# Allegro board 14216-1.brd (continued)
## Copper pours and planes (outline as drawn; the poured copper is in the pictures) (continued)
PWR_5V_LL1 on TOP: 41.57,40.15 41.46,40.26 41.46,41.17 41.68,41.38 43.13,41.38 43.44,41.69 43.44,44.73 43.57,44.85 47.63,44.85 47.76,44.73 47.76,43.46 48.01,43.2 50.3,43.2 50.43,43.08 50.43,40.28 50.3,40.15
PWR_5V_LL1 on BOTTOM: 44.3,40.13 43.7,40.74 43.7,44.35 44.08,44.73 49.79,44.73 50.3,44.22 50.3,40.41 50.02,40.13
PWR_CHG_HIDRV on BOTTOM: 124.49,156.8 126.5,156.8 126.58,156.72 126.58,156.04 126.5,155.96 124.59,155.96 124.44,156.11 124.44,156.75
PWR_CHG_LODRV on BOTTOM: 120.63,162.89 120.53,163 120.53,163.45 120.61,163.53 122.36,163.53 122.46,163.43 122.46,162.92 122.44,162.89
PWR_CHG_PHASE on BOTTOM: 124.54,156.98 124.44,157.08 124.44,159.77 124.14,160.08 123.17,160.08 122.79,160.46 122.79,163.7 123.02,163.93 126.6,163.93 129.04,161.49 129.04,157.59 128,156.54 127.24,156.54 126.8,156.98
PWR_DCBATOUT_1D05V on TOP: 131.99,132.87 131.74,133.12 131.74,138.96 132.12,139.35 135.42,139.35 135.55,139.22 135.55,133 135.42,132.87 ; 2 cut-outs
PWR_DCBATOUT_1D05V on BOTTOM: 132.34,137.26 132.07,137.54 132.07,139.32 132.09,139.35 134.22,139.35 134.58,138.99 134.58,137.49 134.35,137.26
PWR_DCBATOUT_3D3V on TOP: 30.87,43.46 30.21,44.12 30.21,50.4 30.25,50.44 34.42,50.44 34.55,50.31 34.55,43.71 34.3,43.46 ; 2 cut-outs
PWR_DCBATOUT_3D3V on BOTTOM: 34.55,50.44 34.68,50.31 34.68,47.39 34.42,47.14 31.26,47.14 31.04,47.35 31.04,50.07 31.42,50.44
PWR_DCBATOUT_5V on TOP: 48.27,43.46 48.01,43.71 48.01,46.89 47.76,47.14 47.76,51.2 48.14,51.58 51.82,51.58 51.82,43.58 51.7,43.46 ; 2 cut-outs
PWR_DCBATOUT_5V on BOTTOM: 48.27,46.5 48.01,46.76 48.01,47.9 47.76,48.16 47.76,50.06 47.89,50.19 49.92,50.19 50.55,49.55 50.55,46.76 50.3,46.5
PWR_DCBATOUT_VCCCORE on TOP: 115.5,129.44 115.17,129.77 115.17,134.14 115.3,134.27 115.81,134.27 115.82,134.26 117.58,134.26 117.84,134 117.84,129.69 117.58,129.44
PWR_DCBATOUT_VCCCORE on BOTTOM: 115.81,126.01 115.68,126.14 115.68,127.54 115.55,127.66 112.88,127.66 112.63,127.92 112.63,134.78 112.76,134.9 116.47,134.9 116.64,135.07 117.83,135.07 117.96,134.94 117.96,131.98 117.84,131.86 116.82,131.86 116.57,131.6 116.57,126.14 116.44,126.01 ; 2 cut-outs
PWR_DCBATOUT_VGA_CORE1 on TOP: 163.28,92.17 163.02,92.43 163.02,98.14 166.83,98.14 167.22,97.76 173.18,97.76 173.31,97.64 173.31,92.43 173.06,92.17
PWR_DCBATOUT_VGA_CORE1 on BOTTOM: 163.41,92.17 162.9,92.68 162.9,98.02 163.02,98.14 167.72,98.14 168.1,97.76 173.18,97.76 173.31,97.64 173.31,92.3 173.18,92.17 ; 2 cut-outs
PWR_DCBATOUT_VGA_CORE2 on TOP: 167.98,115.29 167.6,115.67 162.52,115.67 162.29,115.9 162.29,120.44 162.36,120.51 164.33,120.51 164.67,120.86 173.24,120.86 173.31,120.79 173.31,115.42 173.18,115.29
PWR_DCBATOUT_VGA_CORE2 on BOTTOM: 167.98,115.29 167.6,115.67 163.02,115.67 162.9,115.8 162.9,120.05 163.1,120.25 166.08,120.25 166.64,120.81 173.25,120.81 173.31,120.74 173.31,115.42 173.18,115.29 ; 2 cut-outs
PWR_VCC_LG on BOTTOM: 120.5,125.38 120.25,125.63 120.25,127.21 120.3,127.26 121.32,127.26 121.39,127.18 121.39,125.51 121.27,125.38
PWR_VCC_PHASE on BOTTOM: 114.26,121.34 114.15,121.44 114.15,124.62 114.41,124.87 115.93,124.87 116.95,125.89 116.95,131.35 117.08,131.47 119.87,131.47 120,131.35 120,125.38 120.89,124.49 120.89,121.44 120.78,121.34
PWR_VCC_UG on BOTTOM: 114.41,125.38 114.26,125.53 114.26,127.21 114.31,127.26 115.27,127.26 115.3,127.23 115.3,125.51 115.17,125.38
PWR_VGA_CORE_LGATE1 on TOP: 168.23,98.27 168.1,98.4 168.1,99.92 169.63,99.92 169.63,98.4 169.5,98.27
PWR_VGA_CORE_LGATE1 on BOTTOM: 168.1,102.97 168.1,104.49 168.23,104.62 169.5,104.62 169.63,104.49 169.63,102.97
PWR_VGA_CORE_LGATE2 on TOP: 168.23,108.56 168.1,108.68 168.1,110.21 169.63,110.21 169.63,108.68 169.5,108.56
PWR_VGA_CORE_LGATE2 on BOTTOM: 168.1,113.26 168.1,114.78 168.23,114.91 169.5,114.91 169.63,114.78 169.63,113.26
PWR_VGA_CORE_PHASE1 on TOP: 173.82,92.43 173.69,92.56 173.69,95.86 173.82,95.98 176.23,95.98 176.49,96.24 176.49,97.13 175.85,97.76 173.82,97.76 173.44,98.14 170.26,98.14 170.01,98.4 170.01,105.13 170.9,106.02 178.9,106.02 179.03,106.02 179.17,105.88 179.17,94.47 177.12,92.43
PWR_VGA_CORE_PHASE1 on BOTTOM: 173.82,93.95 173.69,94.08 173.69,97.89 173.44,98.14 170.26,98.14 170.01,98.4 170.01,103.99 170.14,104.11 173.82,104.11 174.2,104.49 174.2,106.3 174.31,106.42 175.25,106.42 175.27,106.4 175.27,106.13 175.37,106.02 178.98,106.02 179.17,105.83 179.17,94.47 178.65,93.95
PWR_VGA_CORE_PHASE1 on L3: 173.82,93.95 173.69,94.08 173.69,97.89 173.44,98.14 170.26,98.14 170.01,98.4 170.01,103.99 170.14,104.11 178.91,104.11 179.17,103.86 179.17,94.47 178.65,93.95
PWR_VGA_CORE_PHASE2 on TOP: 170.64,106.78 170.14,107.29 170.14,114.4 170.26,114.53 173.44,114.53 173.69,114.78 173.69,119.04 173.69,119.04 173.69,119.21 173.72,119.24 177.35,119.24 179.04,117.54 179.04,117.32 179.05,117.31 179.05,107.13 178.7,106.78
PWR_VGA_CORE_PHASE2 on BOTTOM: 174.31,106.76 174.2,106.88 174.2,108.94 174.07,109.07 170.26,109.07 170.14,109.19 170.14,114.4 170.26,114.53 174.71,114.53 175.6,115.42 176.11,115.42 176.36,115.67 176.36,116.81 176.11,117.07 173.82,117.07 173.69,117.19 173.69,120.39 173.9,120.6 176,120.6 179.05,117.56 179.05,109.88 179.04,109.87 179.04,107.13 178.68,106.77 175.26,106.77 175.25,106.76
PWR_VGA_CORE_PHASE2 on L3: 170.26,109.07 170.14,109.19 170.14,114.4 170.26,114.53 173.57,114.53 173.69,114.65 173.69,120.39 173.9,120.6 176,120.6 179.05,117.56 179.05,109.88 179.05,109.88 179.05,109.38 178.73,109.07
PWR_VGA_CORE_UGATE1 on TOP: 173.69,96.49 173.69,97.25 175.98,97.25 176.11,97.13 176.11,96.62 175.98,96.49
PWR_VGA_CORE_UGATE1 on BOTTOM: 173.69,92.68 173.69,93.44 175.98,93.44 176.11,93.32 176.11,92.81 175.98,92.68
PWR_VGA_CORE_UGATE2 on TOP: 173.79,119.61 173.69,119.71 173.69,120.47 173.73,120.51 175.89,120.51 176.11,120.3 176.11,119.73 175.98,119.61
PWR_VGA_CORE_UGATE2 on BOTTOM: 173.69,115.8 173.69,116.56 175.98,116.56 176.11,116.43 176.11,115.92 175.98,115.8
PWR_VGA_SNUB1 on BOTTOM: 170.66,104.86 170.52,105 170.52,106.4 170.64,106.53 173.48,106.53 173.58,106.42 173.58,104.87 173.57,104.86 ; 2 cut-outs
PWR_VGA_SNUB2 on BOTTOM: 170.79,106.77 170.52,107.03 170.52,108.18 170.77,108.43 173.44,108.43 173.47,108.43 173.58,108.32 173.58,106.77 173.58,106.77 ; 2 cut-outs
REGOUT on TOP: 50.61,170.23 50.57,170.27 50.57,171.42 50.84,171.69 50.84,174.42 51.09,174.67 55.71,174.67 56.04,174.34 56.04,173.04 55.83,172.84 53.68,172.84 53.67,172.84 52.9,172.84 52.75,172.69 52.75,171.39 51.6,170.23 ; 4 cut-outs
RING2 on BOTTOM: 182.52,18.83 182.51,18.83 182.51,19.96 182.08,20.4 182.08,23.6 182.21,23.73 182.76,23.73 182.89,23.6 182.89,21.65 182.73,21.48 182.73,18.85 182.72,18.83 ; 1 cut-out
RING2_R on TOP: 184.61,21.62 184.51,21.72 184.51,22.53 184.61,22.64 187.26,22.64 188.96,24.34 189.67,24.34 190.35,25.02 192.08,25.02 192.13,24.97 192.13,24.59 192.08,24.54 190.69,24.54 190.66,24.52 190.66,24.03 190.71,23.98 192.11,23.98 192.13,23.96 192.13,23.55 192.11,23.52 190.3,23.52 188.39,21.62
RTC_AUX_S5 on TOP: 136.74,58.37 136,59.11 136,66.68 130.75,71.93 130.75,73.66 130.79,73.71 131.45,73.71 131.52,73.64 131.52,72.35 136.63,67.24 136.63,62.72 137.24,62.11 137.24,59.59 137.93,58.91 139.12,58.91 139.41,59.19 139.41,64 139.66,64.24 140.75,64.24 141.56,63.43 141.56,62.45 141.81,62.2 142.79,62.2 142.88,62.11 142.88,59.9 142.87,59.89 142.87,59.35 141.88,58.37 ; 4 cut-outs
RTC_AUX_S5 on BOTTOM: 140.27,59.31 140.16,59.42 140.16,62.44 140.11,62.49 140.11,62.89 140.16,62.95 140.52,62.95 140.75,62.72 140.75,59.42 140.65,59.31
SLEEVE on BOTTOM: 182.92,18.83 182.89,18.85 182.89,21.47 183.05,21.62 183.05,23.86 182.62,24.29 182.62,24.51 182.77,24.66 183.09,24.66 183.86,23.89 183.86,23.6 183.86,23.6 183.86,21.43 183.15,20.72 183.15,18.85 183.12,18.83
SLEEVE_R on TOP: 184.64,23.02 184.54,23.12 184.54,23.98 184.59,24.03 185.55,24.03 187.32,25.81 189.49,25.81 190.71,27.03 192.08,27.03 192.13,26.98 192.13,26.57 192.11,26.55 190.76,26.55 190.71,26.5 190.71,26.06 190.79,25.99 192.11,25.99 192.16,25.94 192.16,25.56 192.13,25.53 190.51,25.53 189.6,24.62 188.73,24.62 187.13,23.02
SP_PLLVDD on TOP: 167,129.24 166.92,129.32 166.92,133.22 165.86,134.27 165.73,134.27 165.59,134.41 165.59,135.28 165.72,135.41 166.17,135.41 166.17,135.41 167.61,135.41 167.88,135.14 167.88,135.14 167.95,135.06 167.95,134.19 168.13,134.01 168.13,133.38 168.3,133.21 168.3,129.53 168,129.24 ; 7 cut-outs
SYS_PRES1# on TOP: 155.74,176.39 155.44,176.68 155.44,180.13 155.53,180.22 156.58,180.22 156.58,180.22 156.66,180.14 156.66,176.49 156.56,176.39
TP_VDD on TOP: 48.58,69.42 48.45,69.54 48.45,70.26 48.57,70.38 55.54,70.38 58.14,72.98 60.04,72.98 61.12,74.06 62.2,74.06 62.29,73.98 63.6,73.98 63.6,73.96 63.69,73.87 63.69,73.64 63.56,73.51 61.77,73.51 60.23,71.97 58.2,71.97 55.65,69.42
TP_VDD on TOP: 48.32,75.41 48.07,75.66 48.07,78.86 48.31,79.1 52.12,79.1 52.38,78.84 52.38,77.23 52.27,77.13 50.89,77.13 49.18,75.41 ; 6 cut-outs
TP_VDD on TOP: 56.13,74.38 56.09,74.42 56.09,76.18 56.17,76.26 57.19,76.26 57.24,76.21 57.24,74.46 57.15,74.38
TP_VDD on L3: 51.25,79.14 52.6,79.14 55.47,76.27 57.38,76.27 57.79,75.86 59.29,75.86 59.87,75.29 59.87,72.3 59.62,72.05 59.26,72.05 58.92,72.39 58.92,74.62 58.31,75.23 55.42,75.23 52.3,78.35 51.25,78.35 51.08,78.53 51.08,78.97
TPAN_VDD on TOP: 77.8,156.74 76.6,157.94 76.6,162.05 76.69,162.14 77.66,162.14 77.81,161.99 77.81,157.62 77.96,157.47 78.84,157.47 78.89,157.42 78.89,156.77 78.86,156.74
TPAN_VDD on BOTTOM: 77.45,160.56 76.82,161.19 71.86,161.19 71.61,161.45 71.61,163.86 71.74,163.99 76.31,163.99 78.09,162.21 78.09,160.81 77.83,160.56 ; 2 cut-outs
TPAN_VDD_F on BOTTOM: 75.67,157.26 74.68,158.25 71.76,158.25 71.48,158.53 71.48,160.05 72.24,160.81 76.82,160.81 78.34,159.29 78.34,157.38 78.21,157.26 ; 5 cut-outs
TPS51216_PHS_SET on TOP: 70.47,14.63 70.09,15.02 69.04,15.02 68.92,15.14 68.92,15.68 69.02,15.78 70.09,15.78 70.47,16.16 71.61,16.16 71.69,16.08 71.69,14.71 71.61,14.63
USB20_VCCA on TOP: 188.46,31.54 187.93,32.08 187.93,34.53 188.07,34.68 189.42,34.68 190.76,36.02 194.65,36.02 194.85,35.82 194.85,32.82 193.57,31.54 ; 4 cut-outs
USB20_VCCA on BOTTOM: 195.54,19.44 195.43,19.54 195.43,29.91 192.94,32.41 192.94,34.35 193.19,34.6 196.27,34.6 198.99,31.89 198.99,24.45 198.08,23.54 198.06,23.54 198,23.47 198,19.54 197.9,19.44
USB30_VCCC on TOP: 18.48,42.04 18.08,42.44 14.58,42.44 13.94,43.08 13.94,45.06 14.35,45.46 23.87,45.46 24.18,45.15 24.18,42.92 23.31,42.05 22.97,42.05 22.97,42.04
USB30_VCCC on BOTTOM: 23.33,42.5 22.88,42.96 15.41,42.96 15.29,43.07 14.38,43.07 13.95,43.5 13.95,44.86 14.54,45.45 22.5,45.45 22.8,45.15 23.57,45.15 23.92,44.8 25.85,44.8 25.99,44.66 25.99,43.44 25.98,43.43 25.98,43.1 25.39,42.5 ; 6 cut-outs
VGA_CORE on TOP: 167.01,139.94 166.85,140.1 166.43,140.1 166.32,139.99 162.66,139.99 162.42,140.23 162.42,140.95 162.48,141.01 169.42,141.01 169.63,140.8 169.63,140.21 169.53,140.12 168.39,140.12 168.22,139.94 ; 1 cut-out
VGA_CORE on TOP: 162.54,125.51 162.41,125.63 162.41,129.32 162.54,129.44 166.61,129.44 166.99,129.06 169.15,129.06 169.4,128.81 169.4,128.55 169.39,128.54 169.39,127.61 168.8,127.02 168.8,126.2 168.59,125.99 164.23,125.99 163.75,125.51 ; 4 cut-outs
VGA_CORE on TOP: 180.2,120.18 180.2,120.19 180.2,120.51 180.55,120.86 185.15,120.86 185.44,120.57 185.44,117.62 185.65,117.41 187.17,117.41 187.59,116.99 187.59,96.35 187.6,96.34 186.13,94.86 184.93,94.86 184.92,94.85 184.49,94.85 182.94,93.3 182.94,92.26 182.66,91.98 180.5,91.98 180.2,92.28
VGA_CORE on TOP: 160.47,142.3 160.39,142.38 160.39,143.35 160.52,143.48 161.28,143.48 161.79,142.97 162.8,142.97 163.2,143.38 164.28,143.38 164.4,143.26 164.91,143.26 165.03,143.38 166.23,143.38 166.4,143.21 166.78,143.21 167.49,143.93 167.89,143.93 168.65,143.16 169.45,143.16 169.59,143.03 169.59,142.44 169.45,142.3 169.45,142.3 161.89,142.3 161.89,142.3 ; 5 cut-outs
VGA_CORE on TOP: 167.22,137.65 166.78,138.09 166.47,138.09 166.04,137.66 165.2,137.66 164.8,138.06 164.44,138.06 164.17,137.78 163.09,137.78 163.09,137.78 163.09,138.08 162.89,138.28 161.37,138.28 161.3,138.35 161.3,138.95 161.44,139.09 162.82,139.09 163.17,138.74 164.19,138.74 164.41,138.95 164.89,138.95 165.08,138.76 166.12,138.76 166.31,138.95 166.79,138.95 167.12,138.61 168.22,138.61 168.56,138.95 168.84,138.95 168.98,138.81 168.98,138.35 168.72,138.09 168.5,138.09 168.06,137.65 ; 2 cut-outs
VGA_CORE on BOTTOM: 180.2,120 181.04,120.84 181.04,121.26 188.98,121.26 189.21,121.03 189.21,119.48 188.22,118.49 188.22,113.34 188.22,113.34 188.22,112.56 188.66,112.12 189.31,112.12 189.5,111.93 189.5,110.66 189.46,110.62 188.47,110.62 187.9,110.05 187.9,105.68 189.34,104.23 189.46,104.23 189.54,104.15 189.54,95.03 189.38,94.87 187.68,94.87 186.54,93.73 184.06,93.73 182.33,92 180.47,92 180.2,92.28 ; 2 cut-outs
VGA_CORE on BOTTOM: 159.44,112.96 159.38,113.02 159.38,120.93 163.33,124.88 168.25,124.88 168.38,124.75 168.38,124.02 168.24,123.88 168.2,123.88 167.04,122.72 164.41,122.72 163.49,121.8 163.08,121.8 162.95,121.94 162.95,122.37 163.91,123.33 163.91,123.79 163.82,123.88 163.34,123.88 159.94,120.48 159.94,113.03 159.87,112.96 ; 1 cut-out
VGA_CORE on BOTTOM: 161.95,134.88 161.31,135.52 161.31,143.9 162.46,145.04 162.84,145.04 163.09,144.79 163.09,144.66 161.7,143.26 161.7,143.14 162.08,142.76 162.33,142.76 164.24,144.66 164.62,144.66 164.74,144.53 164.74,144.28 161.7,141.23 161.7,140.98 161.95,140.72 162.33,140.72 166.14,144.53 166.52,144.53 166.65,144.41 166.65,144.15 161.82,139.33 161.82,138.95 161.95,138.82 162.33,138.82 168.05,144.53 168.3,144.53 168.55,144.28 168.55,144.15 161.82,137.42 161.82,136.91 161.95,136.79 162.33,136.79 170.01,144.47 170.29,144.47 170.45,144.31 170.45,144.02 162.71,136.28 162.71,136.02 162.97,135.77 163.22,135.77 170.08,142.63 170.46,142.63 170.59,142.5 170.59,142.12 164.62,136.15 164.49,136.15 164.24,135.9 164.24,135.64 164.49,135.39 164.87,135.39 170.2,140.72 170.46,140.72 170.71,140.47 170.71,140.34 166.39,136.02 166.39,135.64 166.52,135.52 167.03,135.52 170.2,138.69 170.33,138.69 170.59,138.44 170.59,138.18 168.3,135.9 168.3,135.52 168.43,135.39 168.93,135.39 170.08,136.53 170.33,136.53 170.59,136.28 170.59,136.02 169.44,134.88
VGA_CORE on L2VCC: 180.97,95.06 180.32,95.71 180.32,118.66 176.84,122.14 162.49,122.14 161.59,123.04 161.59,144.35 161.86,144.62 171.35,144.62 171.75,144.22 171.75,142.57 172,142.32 172,139.4 175.28,136.12 175.28,134.23 177.47,132.04 177.56,131.92 179.73,131.92 179.81,131.85 180.85,130.79 180.96,130.68 185.29,130.68 185.99,129.98 186.15,129.98 186.21,130.04 189.3,130.04 189.97,129.37 189.97,119.63 187.63,117.28 187.63,110.83 187.16,110.37 187.16,96.46 185.76,95.06
VGA_CORE on L3: 170.85,123.98 165.68,123.98 164.31,125.35 161.11,125.35 160.93,125.53 160.93,131.68 161.27,132.01 161.27,143.68 161.7,144.11 167.65,144.11 169.14,142.62 169.14,136.07 169.52,135.7 169.52,134.96 169.2,134.65 169.2,133.66 172.84,130.02 177.12,130.02 179.19,127.96 187.94,127.96 190.1,125.8 190.1,117.95 188.27,116.11 188.27,105.26 189.51,104.01 189.51,95.49 188.89,94.87 184.51,94.87 182.94,93.3 182.94,92.28 182.66,92 180.47,92 180.2,92.28 180.2,117.88 176.37,121.71 173.12,121.71
VGA_CORE on L4: 158.87,125.01 158.87,128.32 159.4,128.85 159.4,141.09 160.57,142.26 160.57,143.85 160.87,144.15 169.06,144.15 169.08,144.12 170.21,144.12 171.3,143.03 171.3,133.51 172.07,132.74 172.07,132.32 174.23,130.16 175.8,130.16 177.15,128.81 177.96,128.81 181.69,125.08 183.76,125.08 183.97,125.3 189.69,125.3 190.1,124.89 190.1,117.96 188.27,116.12 188.27,105.24 189.51,103.99 189.51,95.49 188.89,94.86 184.5,94.86 182.94,93.3 182.94,92.31 182.61,91.98 180.5,91.98 180.2,92.28 180.2,117.9 176.29,121.81 162.08,121.81

Small or netless copper shapes (teardrops, artwork), in the pictures only: 17 on TOP, 1 on BOTTOM

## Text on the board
Ref Des/Silkscreen Bottom: F5203:1.1A/24V | F5201:1.1A/24V | X1901:32.768KHZ | X7601:27MHZ | F6201:0.5A/6V | X1801:24MHZ
User.Comments: TONE
Ref Des/Silkscreen Top: X3001:25MHZ | F5501:1.1A/6V | IRIS HSW/BDW | PWB:1XVKN | MADE IN TAIWAN | 14216-1 | REV:A00
User.32: ByImpedance:100.0@_REF_L1=("4.0/6.0(L1)" "3.5/5.0(L1)" "5.0/11.0(L1)")|_REF_L6=("4.0/6.0(L6)" "3.5/5.0(L6)" "5.0/11.0(L6)")|Type="DP"|_REF_L4=("4.0/9.0(L4)" "3.5/7.0(L4)")|_REF_L3=("4.0/9.0(L3)" "3.5/7.0(L3)")|imp="100.0" | ByImpedance:110.0@_REF_L1=("4.0/12.0(L1)")|_REF_L6=("4.0/12.0(L6)")|Type="DP"|_REF_L4=("3.5/13.0(L4)")|_REF_L3=("3.5/13.0(L3)")|imp="110.0" | ByImpedance:33.0@_REF_L1=("12.0(L1)")|_REF_L6=("12.0(L6)")|Type="SE"|_REF_L4=("12.5(L4)")|_REF_L3=("12.5(L3)")|imp="33.0" | ByImpedance:35.0@_REF_L1=("11.0(L1)")|_REF_L6=("11.0(L6)")|Type="SE"|_REF_L4=("10.5(L4)")|_REF_L3=("10.5(L3)")|imp="35.0" | ByImpedance:37.5@_REF_L1=("10.0(L1)")|_REF_L6=("10.0(L6)")|Type="SE"|_REF_L4=("9.5(L4)")|_REF_L3=("9.5(L3)")|imp="37.5" | ByImpedance:40.0@_REF_L1=("8.5(L1)")|_REF_L6=("8.5(L6)")|Type="SE"|_REF_L4=("8.0(L4)")|_REF_L3=("8.0(L3)")|imp="40.0" | ByImpedance:45.0@_REF_L1=("7.0(L1)")|_REF_L6=("7.0(L6)")|Type="SE"|_REF_L4=("6.5(L4)")|_REF_L3=("6.5(L3)")|imp="45.0" | ByImpedance:48.0@_REF_L1=("6.0(L1)")|_REF_L6=("6.0(L6)")|Type="SE"|_REF_L4=("5.5(L4)")|_REF_L3=("5.5(L3)")|imp="48.0" | ByImpedance:50.0@_REF_L1=("5.5(L1)" "5.5(L1)")|_REF_L6=("5.5(L6)" "5.5(L6)")|Type="SE"|_REF_L4=("5.0(L4)")|_REF_L3=("5.0(L3)")|imp="50.0" | ByImpedance:52.0@_REF_L1=("5.0(L1)")|_REF_L6=("5.0(L6)")|Type="SE"|_REF_L4=("4.5(L4)")|_REF_L3=("4.5(L3)")|imp="52.0" | ByImpedance:55.0@_REF_L1=("4.5(L1)")|_REF_L6=("4.5(L6)")|Type="SE"|_REF_L4=("4.0(L4)")|_REF_L3=("4.0(L3)")|imp="55.0" | ByImpedance:60.0@_REF_L1=("3.5(L1)")|_REF_L6=("3.5(L6)")|Type="SE"|_REF_L4=("nil(L4)")|_REF_L3=("nil(L3)")|imp="60.0" | ByImpedance:65.0@_REF_L1=("10.0/5.0(L1)")|_REF_L6=("10.0/5.0(L6)")|Type="DP"|_REF_L4=("9.0/5.0(L4)")|_REF_L3=("9.0/5.0(L3)")|imp="65.0" | ByImpedance:70.0@_REF_L1=("8.5/5.0(L1)")|_REF_L6=("8.5/5.0(L6)")|Type="DP"|_REF_L4=("8.0/5.0(L4)")|_REF_L3=("8.0/5.0(L3)")|imp="70.0" | ByImpedance:72.0@_REF_L1=("8.0/5.0(L1)")|_REF_L6=("8.0/5.0(L6)")|Type="DP"|_REF_L4=("7.0/5.0(L4)")|_REF_L3=("7.0/5.0(L3)")|imp="72.0" | ByImpedance:75.0@_REF_L1=("7.0/4.5(L1)")|_REF_L6=("7.0/4.5(L6)")|Type="DP"|_REF_L4=("7.0/6.0(L4)")|_REF_L3=("7.0/6.0(L3)")|imp="75.0" | ByImpedance:80.0@_REF_L1=("6.0/4.5(L1)")|_REF_L6=("6.0/4.5(L6)")|Type="DP"|_REF_L4=("5.5/5.0(L4)" "6.0/6.0(L4)" "5.0/4.0(L4)")|_REF_L3=("5.5/5.0(L3)" "6.0/6.0(L3)" "5.0/4.0(L3)")|imp="80.0" | ByImpedance:85.0@_REF_L1=("5.5/5.0(L1)" "5.0/4.5(L1)" "6.0/6.0(L1)")|_REF_L6=("5.5/5.0(L6)" "5.0/4.5(L6)" "6.0/6.0(L6)")|Type="DP"|_REF_L4=("5.5/7.0(L4)" "5.0/5.5(L4)" "4.5/4.5(L4)")|_REF_L3=("5.5/7.0(L3)" "5.0/5.5(L3)" "4.5/4.5(L3)")|imp="85.0" | ByImpedance:88.0@_REF_L1=("5.0/5.0(L1)" "4.5/4.0(L1)")|_REF_L6=("5.0/5.0(L6)" "4.5/4.0(L6)")|Type="DP"|_REF_L4=("4.0/4.5(L4)" "5.0/7.0(L4)")|_REF_L3=("4.0/4.5(L3)" "5.0/7.0(L3)")|imp="88.0" | ByImpedance:90.0@_REF_L1=("4.0/4.0(L1)" "5.0/6.0(L1)")|_REF_L6=("4.0/4.0(L6)" "5.0/6.0(L6)")|Type="DP"|_REF_L4=("5.0/8.0(L4)" "4.0/5.0(L4)" "4.5/6.0(L4)")|_REF_L3=("5.0/8.0(L3)" "4.0/5.0(L3)" "4.5/6.0(L3)")|imp="90.0" | ByImpedance:93.0@_REF_L1=("4.0/4.5(L1)" "5.0/6.5(L1)")|_REF_L6=("4.0/4.5(L6)" "5.0/6.5(L6)")|Type="DP"|_REF_L4=("4.0/6.0(L4)")|_REF_L3=("4.0/6.0(L3)")|imp="93.0" | ByImpedance:95.0@_REF_L1=("4.5/6.0(L1)")|_REF_L6=("4.5/6.0(L6)")|Type="DP"|_REF_L4=("4.0/6.5(L4)")|_REF_L3=("4.0/6.5(L3)")|imp="95.0" | LayerIndex:nil | Source:6-1.2-3j.xls | artWorks:("_REF_L3" "_REF_L4" "_REF_L6" "_REF_L1") | gtImpOutlineUsed:BOARD GEOMETRY/PANEL_OUTLINE
User.33: Board Accuracy Check,Nov 17 14:44:51 2014,Passed | Dummy-Static-No Shape On Layer Check,Nov 17 14:44:52 2014,Passed | Split Plane Check,Nov 17 14:44:51 2014,Passed
User.38: This gerber is just for your reference to find the DP impedance traces in layer L1. | DP IMPEDANCE TABLE: L1 | * - Denotes that this Impedance | is NOT used | IMP(Ohm) | *65.0 | *70.0 | *72.0 | *75.0 | 80.0 | *85.0 | 85.0 | *88.0 | 90.0 | *90.0 | *93.0 | *95.0 | *100.0 | 100.0 | *110.0 | WIDTH(mils) | 10.0/5.0 | 8.5/5.0 | 8.0/5.0 | 7.0/4.5 | 6.0/4.5 | 5.5/5.0 | 5.0/4.5 | 6.0/6.0 | 5.0/5.0 | 4.5/4.0 | 4.0/4.0 | 5.0/6.0 | 4.0/4.5 | 5.0/6.5 | 4.5/6.0 | 4.0/6.0 | 3.5/5.0 | 5.0/11.0 | 4.0/12.0 | TYPE | DP
User.40: This gerber is just for your reference to find the SE impedance traces in layer L1. | SE IMPEDANCE TABLE: L1 | * - Denotes that this Impedance | is NOT used | IMP(Ohm) | *33.0 | *35.0 | *37.5 | 40.0 | 45.0 | *48.0 | 50.0 | *52.0 | *55.0 | *60.0 | WIDTH(mils) | 12.0 | 11.0 | 10.0 | 8.5 | 7.0 | 6.0 | 5.5 | 5.0 | 4.5 | 3.5 | TYPE | SE
User.42: This gerber is just for your reference to find the DP impedance traces in layer L3. | DP IMPEDANCE TABLE: L3 | * - Denotes that this Impedance | is NOT used | IMP(Ohm) | *65.0 | *70.0 | *72.0 | *75.0 | *80.0 | 80.0 | *85.0 | 85.0 | *88.0 | *90.0 | *93.0 | *95.0 | *100.0 | *110.0 | WIDTH(mils) | 9.0/5.0 | 8.0/5.0 | 7.0/5.0 | 7.0/6.0 | 5.5/5.0 | 6.0/6.0 | 5.0/4.0 | 5.5/7.0 | 5.0/5.5 | 4.5/4.5 | 4.0/4.5 | 5.0/7.0 | 5.0/8.0 | 4.0/5.0 | 4.5/6.0 | 4.0/6.0 | 4.0/6.5 | 4.0/9.0 | 3.5/7.0 | 3.5/13.0 | TYPE | DP
User.44: This gerber is just for your reference to find the SE impedance traces in layer L3. | SE IMPEDANCE TABLE: L3 | * - Denotes that this Impedance | is NOT used | IMP(Ohm) | *33.0 | *35.0 | *37.5 | 40.0 | 45.0 | *48.0 | 50.0 | *52.0 | *55.0 | *60.0 | WIDTH(mils) | 12.5 | 10.5 | 9.5 | 8.0 | 6.5 | 5.5 | 5.0 | 4.5 | 4.0 | nil | TYPE | SE
User.45: Note:Refer to DRILL layer for ELLIPSE drill direction | FIGURE | SIZE | 10.0 | 16.0 | 20.0 | 24.0 | 28.0 | 36.0 | 48.0 | 115.0 | 117.0 | 126.0 | 166.0 | 182.0 | 44.0 | 46.0 | 52.0 | 56.0 | 63.0 | 65.0 | 86.0 | 158.0 | 60.0x36.0 | 67.0x36.0 | 71.0x36.0 | 90.0x28.0 | 95.0x28.0 | 95.0x36.0 | 110.0x40.0 | 130.0x24.0 | 150.0x119.0 | DRILL CHART: TOP to BOTTOM | ALL UNITS ARE IN MILS | PLATED | NON-PLATED | QTY | 3964 | 982 | 19 | 15 | 9 | 8 | 4 | 3 | 2 | 1 | 5 | 6 | This gerber is just for your reference to find the DP impedance traces in layer L4. | This gerber is just for your reference to find the DP impedance traces in layer L6. | This gerber is just for your reference to find the SE impedance traces in layer L4. | This gerber is just for your reference to find the SE impedance traces in layer L6. | DP IMPEDANCE TABLE: L4 | DP IMPEDANCE TABLE: L6 | SE IMPEDANCE TABLE: L4 | SE IMPEDANCE TABLE: L6 | * - Denotes that this Impedance | is NOT used | Model | IRIS HSW/BDW | PCB_NO | 14216 | VER. | Layer | DRILL | L1 | L2VCC | L3 | TMASK | TPLACE | TSILK | TSMD | Designer | CyRiL | Date | 11/17/2014 | IMP(Ohm) | *33.0 | *65.0 | *35.0 | *70.0 | *37.5 | *72.0 | *40.0 | *75.0 | 40.0 | *80.0 | 45.0 | 80.0 | *48.0 | *85.0 | 50.0 | 85.0 | *52.0 | *55.0 | *88.0 | *60.0 | 90.0 | *90.0 | *93.0 | *95.0 | *100.0 | 100.0 | *110.0 | WIDTH(mils) | 12.0 | 12.5 | 10.5 | 11.0 | 9.5 | 8.0 | 8.5 | 6.5 | 7.0 | 5.5 | 6.0 | 5.0 | 4.5 | 4.0 | nil | 3.5 | 10.0/5.0 | 9.0/5.0 | 8.0/5.0 | 8.5/5.0 | 7.0/5.0 | 7.0/4.5 | 7.0/6.0 | 5.5/5.0 | 6.0/4.5 | 6.0/6.0 | 5.0/4.0 | 5.0/4.5 | 5.5/7.0 | 5.0/5.0 | 5.0/5.5 | 4.5/4.0 | 4.5/4.5 | 4.0/4.0 | 4.0/4.5 | 5.0/6.0 | 5.0/7.0 | 5.0/8.0 | 4.0/5.0 | 5.0/6.5 | 4.5/6.0 | 4.0/6.0 | 3.5/5.0 | 4.0/6.5 | 4.0/9.0 | 5.0/11.0 | 3.5/7.0 | 4.0/12.0 | 3.5/13.0 | TYPE | SE | DP | BMASK | BPLACE | BSILK | BSMD | L4 | L5GND | L6
